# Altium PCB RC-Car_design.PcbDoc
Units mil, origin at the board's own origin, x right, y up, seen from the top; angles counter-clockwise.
Board outline 2760 x 1970 mil, 2 copper layers (Top Layer, Bottom Layer); 27 components, 22 nets, 111 pads, 0 vias.
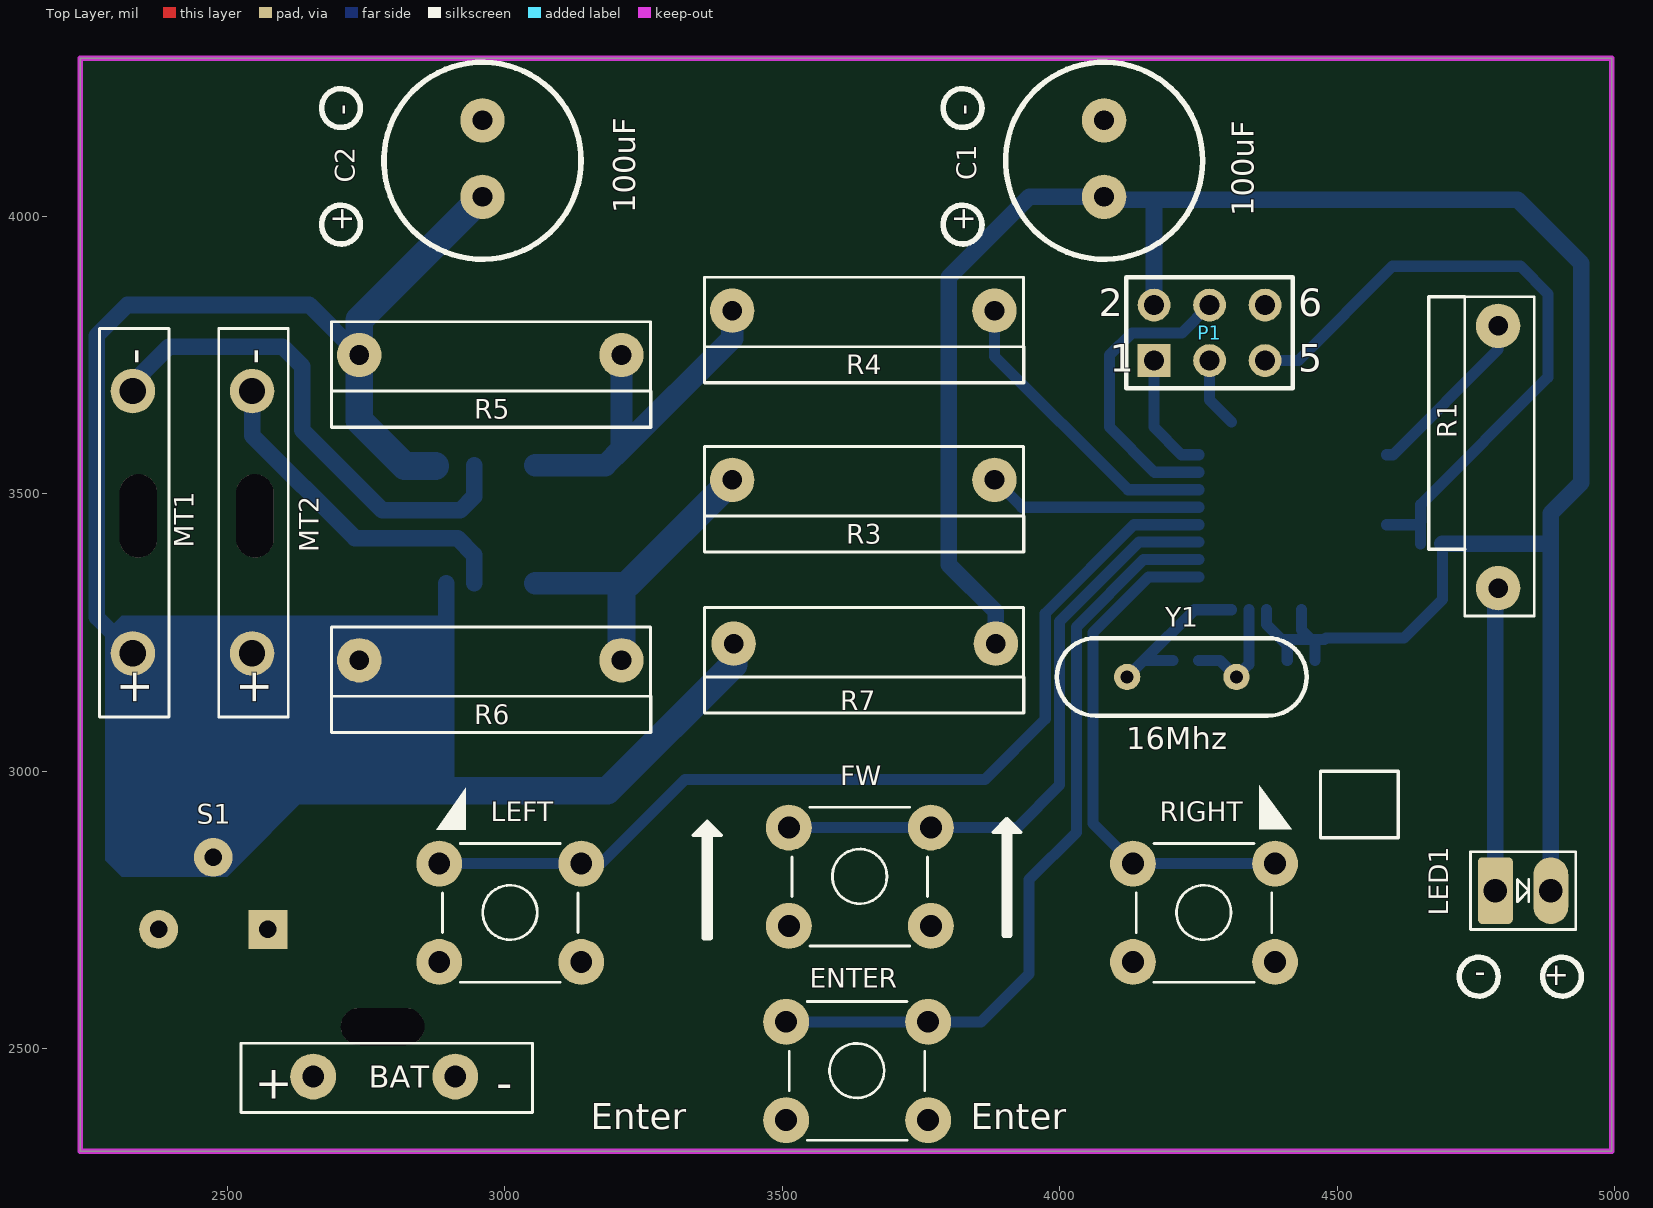
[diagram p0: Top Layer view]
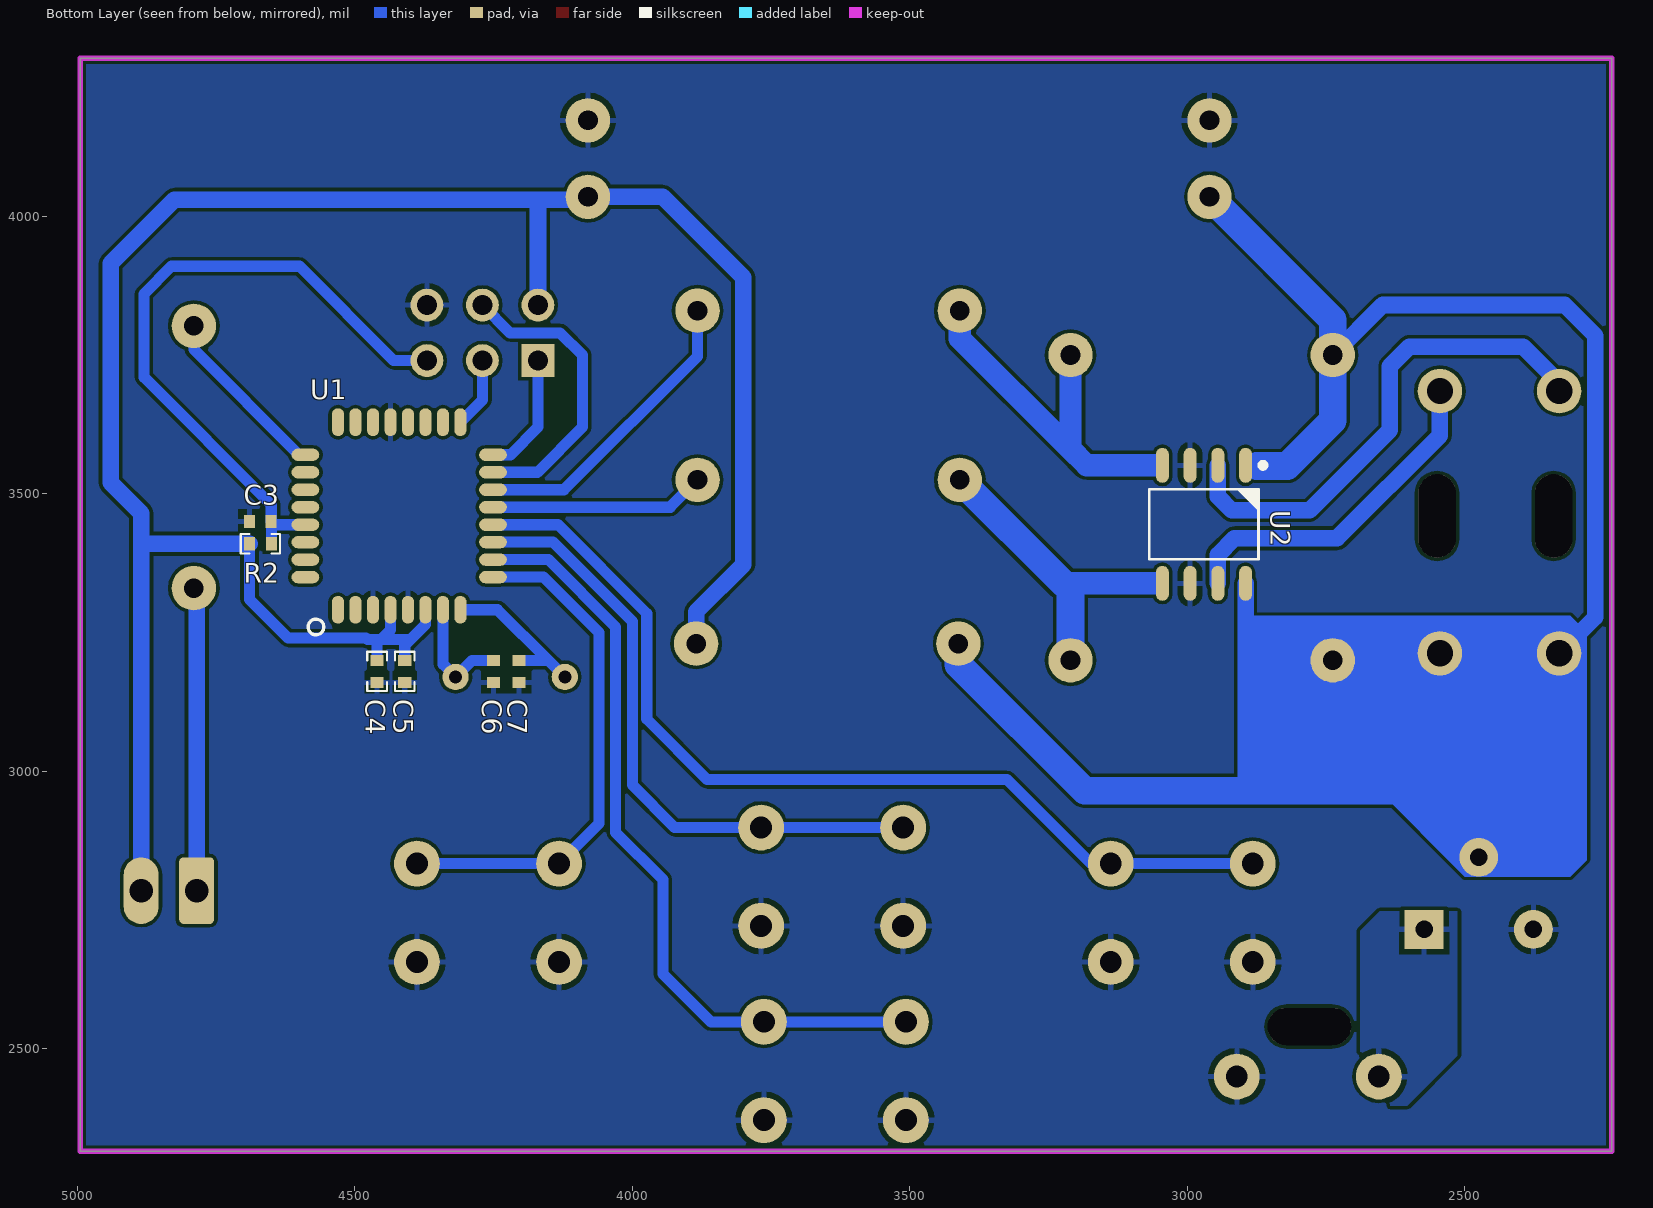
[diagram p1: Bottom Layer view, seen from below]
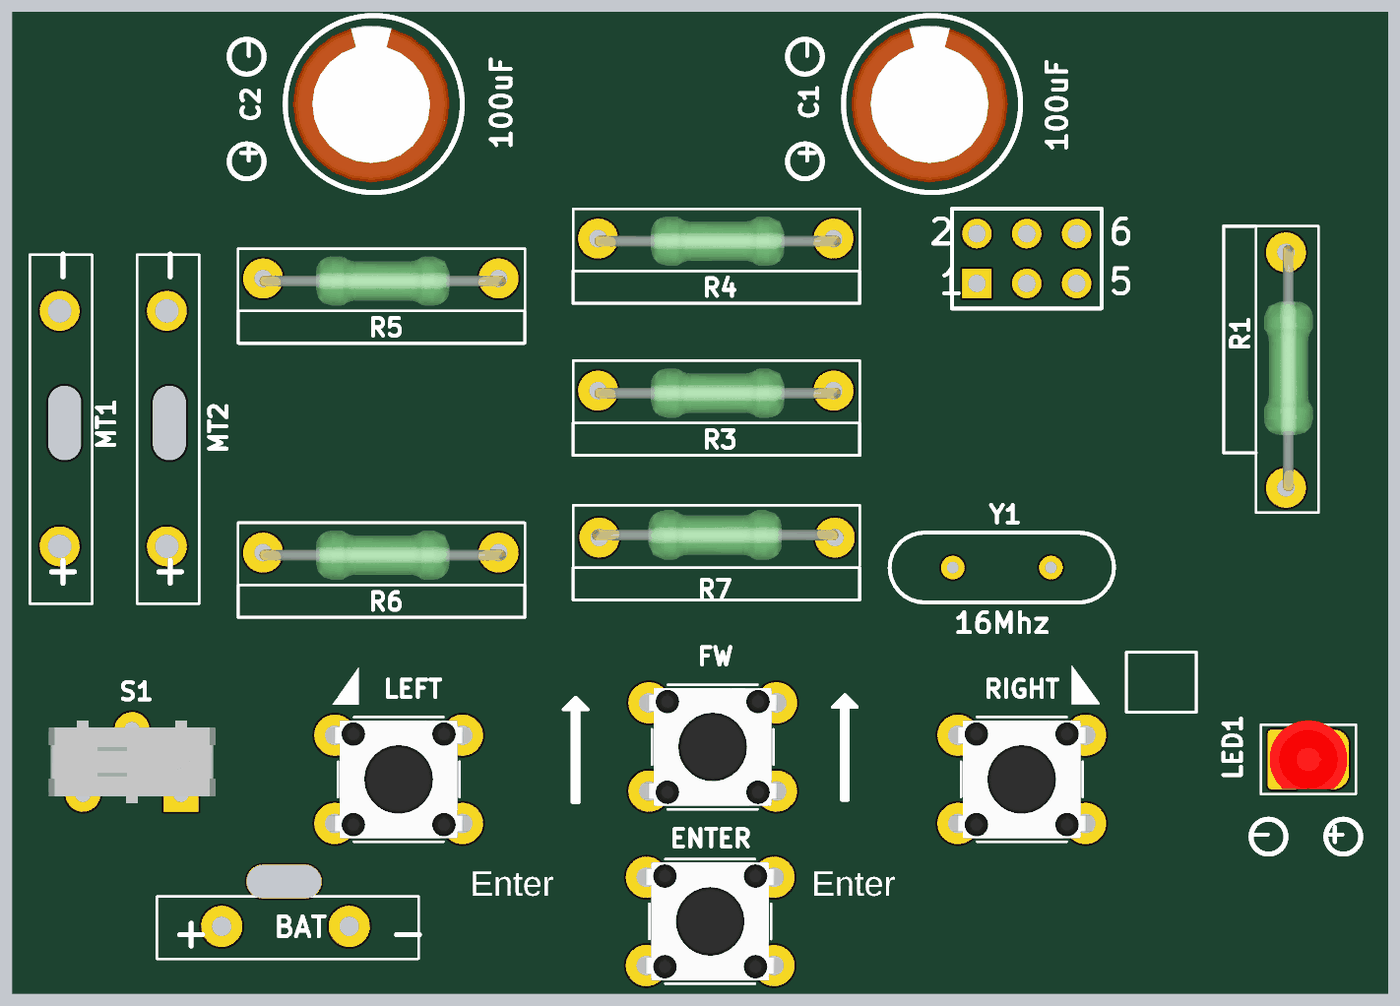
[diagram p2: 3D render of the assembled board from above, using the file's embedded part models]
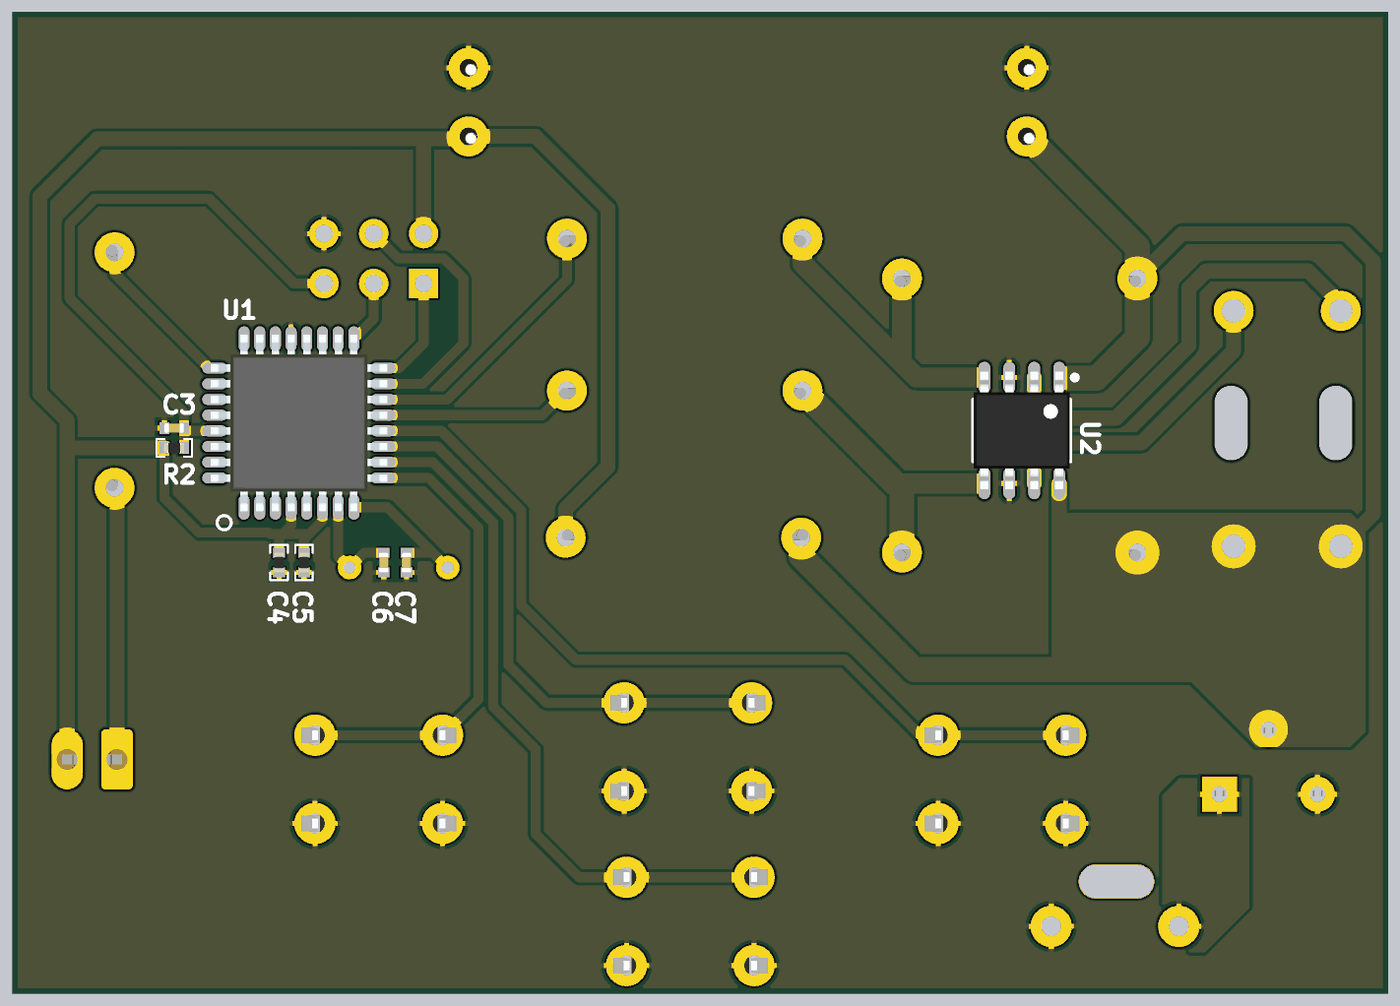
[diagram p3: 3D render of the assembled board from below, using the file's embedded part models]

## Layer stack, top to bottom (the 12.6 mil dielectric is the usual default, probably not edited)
Top Solder: solder mask 0.4, Solder Resist, Dk 3.5
Top Layer: signal copper 1.4
Dielectric 1: dielectric 12.6, FR-4, Dk 4.8
Bottom Layer: signal copper 1.4
Bottom Solder: solder mask 0.4, Solder Resist, Dk 3.5

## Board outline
2235,2315 4995,2315 4995,4285 2235,4285

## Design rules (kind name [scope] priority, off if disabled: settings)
Clearance [All] p1: gap=6 ignorepadtopadclearanceinfootprint=FALSE except(0: Arc-Hole Track-Hole SMDPad-Hole THPad-Hole Via-Hole Fill-Hole Poly-Hole Region-Hole Text-Hole)
HoleSize [All] p1: absolutevalues=TRUE maxlimit=300 minlimit=1 maxpercent=80.000 minpercent=20.000
MinimumSolderMaskSliver [All] p1 off: minsoldermaskwidth=10
PolygonConnect [All] p1: connectstyle=Relief reliefconductorwidth=10 reliefentries=4 polygonreliefangle="90 Angle" airgapwidth=10
RoutingVias [All] p1: holewidth=28 width=50 viastyle="Through Hole" minholewidth=28 minwidth=50 maxholewidth=28 maxwidth=50
SilkToSilkClearance [All] p1 off: silktosilkclearance=10
SilkToSolderMaskClearance [IsPad] p1 off: minsilkscreentomaskgap=10 clearancetoexposedcopper=TRUE
SolderMaskExpansion [All] p1: expansion=4
Width [All] p1: maxlimit=50 minlimit=10 preferedwidth=10 minimp=50.000000 maximp=50.000000 favimp=50.000000
26 further rules are at their usual default settings.

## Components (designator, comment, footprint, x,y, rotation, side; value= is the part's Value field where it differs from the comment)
BAT "Hole 2P" Header_pitch7mm_hole1.2mm 2785,2450 r0 top
C1 "" Picth3.5_D8_H12_Al_condensor 4080,4035 r90 top value=100uF
C2 "" Picth3.5_D8_H12_Al_condensor 2960,4035 r90 top value=1000uF
C3 "Cap Semi" C0402 4670.31,3450 r0 bottom value=100nF
C4 "Cap Semi" R0402 4460,3180 r90 bottom value=100nF
C5 "Cap Semi" R0402 4410,3180 r90 bottom value=100nF
C6 "Cap Semi" C0402 4250,3180 r270 bottom value=22pF
C7 "Cap Semi" C0402 4204.22,3180 r270 bottom value=22pF
ENTER "EVQ-PQHB55" TACT_SWITCH_TL-1105-C 3635,2460 r0 top
FW "EVQ-PQHB55" TACT_SWITCH_TL-1105-C 3640,2810 r0 top
LED1 "red" HDR_1x2_LED 4785,2785 r90 top
LEFT "EVQ-PQHB55" TACT_SWITCH_TL-1105-C 3010,2745 r0 top
MT1 "Hole 2P" Header_pitch12mm_hole1.2mm 2330,3212.56 r90 top
MT2 "Hole 2P" Header_pitch12mm_hole1.2mm 2545,3212.56 r90 top
P1 "Header 3X2" HDR2X3 4170,3740 r0 top
R1 "Res Semi" "METAL FILM RESISTOR_2X12MM" 4790,3330 r90 top value=560R
R2 "Res0402" R0402 4670,3410 r0 bottom value=10k
R3 "Res Semi" "METAL FILM RESISTOR_2X12MM" 3410,3525 r0 top value=4.7k
R4 "Res Semi" "METAL FILM RESISTOR_2X12MM" 3410,3830 r0 top value=4.7k
R5 "Res Semi" "METAL FILM RESISTOR_2X12MM" 2738,3750 r0 top value=47K
R6 "Res Semi" "METAL FILM RESISTOR_2X12MM" 2738,3200 r0 top value=47K
R7 "Res Semi" "METAL FILM RESISTOR_2X12MM" 3885,3230 r180 top value=220R
RIGHT "EVQ-PQHB55" TACT_SWITCH_TL-1105-C 4260,2745 r0 top
S1 "1825116-1" "SS-12D1505-G 2" 2475,2780 r180 top
U1 "ATMEGA328P-A" ATMEGA328P 4420,3460 r90 bottom
U2 "CRM2506" SOIC127P600X175-8AN 2970,3445 r270 bottom
Y1 "16MHz" XTAL16 4220,3170 r0 top

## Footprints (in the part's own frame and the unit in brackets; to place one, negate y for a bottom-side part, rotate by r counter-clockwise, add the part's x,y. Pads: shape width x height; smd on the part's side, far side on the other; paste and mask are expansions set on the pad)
ATMEGA328P [mil]
  oval 50x22 smd: 1(-169,110.24) 2(-169,78.74) 3(-169,47.24) 4(-169,15.75) 5(-169,-15.75) 6(-169,-47.24) 7(-169,-78.74) 8(-169,-110.24) 17(169,-110.24) 18(169,-78.74) 19(169,-47.24) 20(169,-15.75) 21(169,15.75) 22(169,47.24) 23(169,78.74) 24(169,110.24)
  oval 22x50 smd: 9(-110.24,-169) 10(-78.74,-169) 11(-47.24,-169) 12(-15.75,-169) 13(15.75,-169) 14(47.24,-169) 15(78.74,-169) 16(110.24,-169) 25(110.24,169) 26(78.74,169) 27(47.24,169) 28(15.75,169) 29(-15.75,169) 30(-47.24,169) 31(-78.74,169) 32(-110.24,169)
  body extent -177,-177 177,177, height 47
C0402 [mm]
  rect 0.5x0.6 smd mask+0.1: 1(-0.5,0) 2(0.5,0)
  body extent -0.5,-0.25 0.5,0.25, height 0.47
HDR2X3 [mm] "Connector; Header; 3x2 Position"
  rect 1.5x1.5 hole 0.9: 1(0,0)
  round 1.5 hole 0.9: 2(0,2.54) 3(2.54,0) 4(2.54,2.54) 5(5.08,0) 6(5.08,2.54)
  silkscreen extent -1.27,-1.27 6.35,3.81
HDR_1x2_LED [mil] "Connector Header, Single-row 2-position, 0.100\" pitch"
  rrect25% 120x63 hole 42: A(0,0)
  oval 120x63 hole 42: K(0,-100)
  silkscreen extent -70,-145 70,45, body extent -59,-128 79,29, height 212
Header_pitch7mm_hole1.2mm [mm]
  round 2.1 hole 1: 1(-3.302,0) 2(3.198,0)
  silkscreen extent -6.6,-1.65 6.73,1.52
Header_pitch12mm_hole1.2mm [mil]
  round 80 hole 47.24: 1(0,0) 2(472.44,0)
  silkscreen extent -115,-65 585,60
"METAL FILM RESISTOR_2X12MM" [mil]
  round 80 hole 35.43: 1(0,0) 2(472.44,0)
  silkscreen extent -50,-65 525,60, body extent -7,-54 487,44, height 110
Picth3.5_D8_H12_Al_condensor [mil]
  round 80 hole 35.43: 1(0,0) 2(137.8,0)
  silkscreen extent -113,-178 243,177, body extent -92,-152 222,162, height 455
R0402 [mm]
  rect 0.5x0.6 smd mask+0.1: 1(-0.5,0) 2(0.5,0)
  silkscreen extent -0.9,-0.45 0.9,0.45, body extent -0.5,-0.25 0.5,0.26, height 0.33
SOIC127P600X175-8AN [mm] "SOIC, 8-Leads, Body 4.9x3.9mm, Pitch 1.27mm, IPC Medium Density"
  round 1 on Mech15: 0(0,0)
  oval 1.6x0.6 smd: 1(-2.7,1.905) 2(-2.7,0.635) 3(-2.7,-0.635) 4(-2.7,-1.905) 5(2.7,-1.905) 6(2.7,-0.635) 7(2.7,0.635) 8(2.7,1.905)
  silkscreen extent -2.82,-2.5 1.6,2.82, body extent -3,-2.45 3,2.45, height 1.75
"SS-12D1505-G 2" [mm] "SWITCH SLIDE DPDT 300MA 6V"
  rect 1.778x1.778 hole 0.8: 1(-2.5,1.65)
  round 1.778 hole 0.8: 2(0,-1.65) 3(2.5,1.65)
  body extent -4.25,-2.1 4.25,2.1, height 5.47
TACT_SWITCH_TL-1105-C [mm] "E-Switch TL1105 series tact switch 8.0mm stem height"
  round 0.508 on Mech15: 0(0,0)
  round 2.1 hole 1: 1(-3.25,-2.25) 1(3.25,-2.25) 2(-3.25,2.25) 2(3.25,2.25)
  silkscreen extent -3.1,-3.17 3.1,3.17, body extent -3.95,-3 3.95,3, height 8
XTAL16 [mm]
  round 1.2 hole 0.6: 1(-2.5,0) 2(2.5,0)
  silkscreen extent -5.71,-1.78 5.71,1.78

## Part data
BAT MT1 MT2: "Header, 2-Pin"
C1: library part "CAP ELEC6.3*4.2", Voltage=50V
C2: library part "CAP ELEC6.3*4.2", Voltage=10V
C3 C4 C5 C6 C7: "Capacitor (Semiconductor SIM Model)"
ENTER FW LEFT RIGHT: library part "SMD4*4*1.5 4p", "Low-profile captive tact switch", Contact Rating @ Voltage="0.02A @ 15VDC", Manufacturer 1="Panasonic - ECG", Operating Force=160gf, Package / Case="per dwg", Ratings="1.6 Newton"
LED1: library part LED_SMD_Yellow_0603_150mcd, "LED 0603 SMD Yellow 590nm 150mcd 20mA"
P1: "Header, 3-Pin, Dual row"
R1 R2 R3 R4 R5 R6 R7: "Semiconductor Resistor"
S1: "Slide Switch SPDT Through Hole, Right Angle", Contact Current Rating=300mA, Manufacturer="ITT C&K", Manufacturer Part Number=SS12D1505G2, Max Operating Temperature=70°C, Min Operating Temperature=-20°C, Operating Force=200gf, Package Quantity=500, Supplier Part Number 1=CKN10372-ND, Voltage Rating (DC)=6V
U1: "IC, SWITCH, SPDT ANA, SMD", Case/Package=TQFP, Frequency=20MHz, Manufacturer="Microchip / Atmel", Manufacturer Part Number=ATMEGA328PB-AUR, Max Operating Temperature=85°C, Max Supply Voltage=5.5V, Min Operating Temperature=-40°C, Min Supply Voltage=1.8V, Operating Supply Voltage=5V, Supplier Part Number 1=ATMEGA328PB-AURCT-ND
Y1: library part XTAL, "Crystal Oscillator"

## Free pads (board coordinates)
  oval 66.93x150 hole 66.93 slot 150 at 90 deg unplated: 2(2340,3460) 2(2550,3460)
  oval 150x66.93 hole 66.93 slot 150 at 0 deg: 2(2780,2540)

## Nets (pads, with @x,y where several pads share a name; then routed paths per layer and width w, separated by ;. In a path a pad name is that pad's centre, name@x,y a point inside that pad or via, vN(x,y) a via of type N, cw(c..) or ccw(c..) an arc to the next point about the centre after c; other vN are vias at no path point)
ENTER: ENTER.2 U1.10 | length 1405.2
  Bottom Layer w20: ENTER.2@3507.05,2548.58 3762.95,2548.58 3858.58,2548.58 3945,2635 3945,2805 4030,2890 4030,3260 4151.26,3381.26 U1.10
FW: FW.2 U1.11 | length 1124.7
  Bottom Layer w20: FW.2@3512.05,2898.58 3767.95,2898.58 3923.58,2898.58 4000,2975 4000,3270 4142.76,3412.76 U1.11
GND: BAT.2 C1.2 C2.2 C3.2 C4.1 C5.1 C6.2 C7.2 ENTER.1 FW.1 LEFT.1 P1.6 RIGHT.1 S1.3 U1.3 U1.5 U1.21 U2.3 U2.6
InA: R4.1 R5.2 U2.4 | length 668.1
  Bottom Layer w40: U2.4@3055,3551.3 3181.3,3551.3 3212.5,3582.5 ; R5.2 3210.44,3584.56 3212.5,3582.5 ; R4.1 3410,3780 3212.5,3582.5
InB: R3.1 R6.2 U2.5 | length 576.4
  Bottom Layer w30: 3210.44,3325.44 3223.7,3338.7
  Bottom Layer w40: U2.5@3055,3338.7 3223.7,3338.7
  Bottom Layer w50: R6.2 3210.44,3325.44 ; 3223.7,3338.7 R3.1
LEFT: LEFT.2 U1.12 | length 1733.2
  Bottom Layer w20: LEFT.2@2882.05,2833.58 3137.95,2833.58 3173.58,2833.58 3325,2985 3865,2985 3974,3094 3974,3284 4134.25,3444.25 U1.12
MISO: P1.1 U1.16 | length 221.6
  Bottom Layer w20: P1.1 4170,3620 4219.76,3570.24 U1.16
MOSI: P1.4 U1.15 | length 541.9
  Bottom Layer w20: U1.15 4171.26,3538.74 4090,3620 4090,3750 4130,3790 4220,3790 P1.4
NetBAT_1: BAT.1 S1.1
NetC6_1: C6.1 U1.7 Y1.2 | length 211.2
  Bottom Layer w20: C6.1 4288.74,3199.69 Y1.2 4341.26,3192.83 U1.7
NetC7_1: C7.1 U1.8 Y1.1 | length 291.3
  Bottom Layer w20: Y1.1 4151.26,3199.69 ; C7.1 4151.26,3199.69 ; U1.8 4242.57,3291 4151.26,3199.69
NetLED1_A: LED1.A R1.1 | length 547.1
  Bottom Layer w30: LED1.A 4785,3325 R1.1
NetMT1_2: MT1.2 U2.2 | length 919.4
  Bottom Layer w30: MT1.2@2315,3685 2395,3765 2600,3765 2635,3730 2635,3615 2780,3470 2920,3470 2945,3495 U2.2
NetMT2_2: MT2.2 U2.7 | length 620.4
  Bottom Layer w30: MT2.2 2545,3605 2730,3420 2915,3420 2945,3390 U2.7
NetR1_2: R1.2 U1.25 | length 322
  Bottom Layer w20: U1.25 4600.24,3570.24 4790,3760 R1.2
NetR3_2: R3.2 U1.13 | length 389
  Bottom Layer w20: R3.2 3931.69,3475.75 U1.13
NetR4_2: R4.2 U1.14 | length 550.5
  Bottom Layer w20: R4.2 3882.44,3747.56 4122.76,3507.24 U1.14
RESET: C3.1 P1.5 R2.1 U1.29 | length 1209.8
  Bottom Layer w20: P1.5 4430,3740 4600,3910 4830,3910 4880,3860 4880,3710 4650.63,3480.63 C3.1 C3.1@4650.31,3449.69 ; U1.29 4644.88,3444.25 C3.1@4650.31,3449.69 ; R2.1 C3.1@4650.31,3449.69
RIGHT: RIGHT.2 U1.9 | length 934.5
  Bottom Layer w20: U1.9 4159.76,3349.76 4060,3250 4060,2905.63 4132.05,2833.58 RIGHT.2@4387.95,2833.58
SCK: P1.3 U1.17 | length 127.5
  Bottom Layer w20: P1.3 4270,3668.76 U1.17
VCC: C2.1 MT1.1 MT2.1 R5.1 R6.1 R7.2 S1.2 U2.1 U2.8 | length 3727
  Bottom Layer w30: MT1.1 2265,3277.56 2265,3785 2320,3840 2648,3840 R5.1 ; 2890,2965 2895,2970 U2.8
  Bottom Layer w50: MT1.1@2315,3212.56 2315,3004.96 S1.2 2595.04,2965 2890,2965 3185,2965 3412.56,3192.56 R7.2 ; 2875,3550 2820,3550 2738,3632 R5.1 2738,3813 C2.1
VDD: C1.1 C4.2 C5.2 LED1.K P1.2 R2.2 R7.1 U1.4 U1.6 | length 4094.8
  Bottom Layer w20: U1.6 4372.76,3264.65 4400,3237.41 ; C5.2 4410,3227.41 4400,3237.41 ; U1.4 4435.75,3254.25 4450,3240 ; C4.2 4460,3230 ; R2.2 4689.69,3309.69 4620,3240 4480,3240 4477.41,3237.41 4400,3237.41
  Bottom Layer w30: R7.1 3885,3287.44 3800,3372.44 3800,3890 3945,4035 C1.1 ; C1.1@4080,4030 4170,4030 ; P1.2 4170,4030 ; R2.2 4885,3410 ; LED1.K 4885,3410 ; 4170,4030 4824.75,4030 4940,3914.75 4940,3520 4885,3465 4885,3410
pads on no net: ENTER.0 FW.0 LEFT.0 RIGHT.0 U1.1 U1.2 U1.18 U1.19 U1.20 U1.22 U1.23 U1.24 U1.26 U1.27 U1.28 U1.30 U1.31 U1.32 U2.0

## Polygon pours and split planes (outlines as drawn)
NetBAT_1 on Bottom Layer "Bottom Layer-No Net" (solid, remove dead copper, pour order 0): 2653.39,2747.66 2688.39,2712.66 2688.39,2417.66 2668.39,2397.66 2603.39,2397.66 2513.39,2487.66 2513.39,2747.66
GND on Bottom Layer "Bottom Layer-No Net" (solid, remove dead copper, pour order 6): 2234.71,2314.71 2234.71,4284.71 4994.71,4284.71 4994.71,2314.71

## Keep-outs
Keep-Out Layer:
  the board outline again, w10

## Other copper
Bottom Layer:
  region net VCC: 2895,2970 2660,2970 2500,2810 2310,2810 2280,2840 2280,3250 2310,3280 2895,3280

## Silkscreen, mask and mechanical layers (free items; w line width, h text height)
Top Overlay:
  circle w10: c3825,3985 r35
  circle w10: c3825,4195 r35
  circle w10: c2705,4195 r35
  circle w10: c2705,3985 r35
  circle w10: c4755,2630 r35
  circle w10: c4905,2630 r35
  region: 3365,2910 3340,2885 3390,2885
  region: 3905,2915 3880,2890 3930,2890
  region: 2930,2895 2876.85,2895 2930,2970.53
  region: 4360,2895.45 4360,2974.55 4418,2895.45
  lines w6: 2688,3135 2688,3070 3263,3070 3263,3135 ; 2688,3685 2688,3620 3263,3620 3263,3685 ; 3360,3170 3360,3105 3935,3105 3935,3170 ; 3360,3460 3360,3395 3935,3395 3935,3460 ; 3360,3765 3360,3700 3935,3700 3935,3765 ; 4730,3400 4665,3400 4665,3855 4730,3855 ; 3340,2885 3365,2910 3390,2885 3340,2885 ; 3880,2890 3930,2890 3905,2915 3880,2890 ; 4470,2880 4470,3000 4610,3000 4610,2880 4470,2880
  lines w10: 3360,2885 3360,2700 3370,2700 3370,2885 ; 3900,2890 3900,2705 3910,2705 3910,2890
  text "-" at 2725,4182 h40 r90
  text "-" at 3845,4182 h40 r90
  text "100uF" at 3235,4005 h40 r90
  text "100uF" at 4350,4000 h40 r90
  text "+" at 2725,3972 h40 r90
  text "+" at 3845,3972 h40 r90
  text "16Mhz" at 4120,3040 h40
  text "-" at 4768,2650 h40 r180
  text "+" at 4918,2650 h40 r180
  text "Enter" at 3155,2340 h80
  text "Enter" at 3840,2340 h80
Bottom Overlay:
  circle w6: c4570,3260 r14.14

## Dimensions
4995,4285 to 4995,2315 on Mechanical 13
2235,4285 to 4995,4285 on Mechanical 13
